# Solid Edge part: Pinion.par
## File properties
Author: Admin
Template: SEER_ExtSpurGear.par
Last saved by: Admin
Revision: 3
Application: Solid Edge
Density: 7833.000 kg/m^3
Accuracy: 0.990
SEER_Parameters: SEERSG2#ER#4#ER#0.349065850398866#ER#0.003#ER#0.032#ER#0#ER#0.001#ER#0#ER#1#ER#1.2#ER#0.8#ER#10000#ER#1#ER#1#ER#30#ER#120#ER#0.0024#ER#0.0064#ER#0.01#ER#0.014#ER#0#ER#0#ER#6#ER#1000#ER#104.71975511966#ER#104.71975511966#ER#9.54#ER#9.54#ER#0.92#ER#1#ER#1#ER#1#ER#1#ER#0#ER#0#ER#1#ER#0#ER#0#ER#1#ER#0#ER#0#ER#0.08#ER#0.08#ER#0.008#ER#0.008#ER#0.025#ER#0.025#ER#0#ER#1140#ER#605#ER#0#ER#1140#ER#390#ER#12#ER#SweptProtrusion_1#ER#Pattern_1#ER#SweptProtrusion_1#ER#Pattern_1#ER##ER#E:\Project\3D\SoccerBot\Hardware\Gear.par#ER#0#ER#0#ER#ExtrudedProtrusion_4#ER#ExtrudedCutout_5#ER#ExtrudedProtrusion_4#ER#ExtrudedCutout_5#ER#0#ER#1#ER#0#ER#0#ER#False#ER#0
Username: Admin
Material: Steel
Face Style: Steel
Fill Style: ANSI32(Steel)
Virtual Style: Machined steel
Coef. of Thermal Exp: 1.3e-05
Thermal Conductivity: 32.0
Specific Heat: 481.0
Modulus of Elasticity: 199947953000.0
Poission's Ratio: 0.29
Yield Stress: 262000766.0
Ultimate Stress: 358527364.0
Elongation: 0.0
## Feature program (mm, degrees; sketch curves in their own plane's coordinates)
sketch for "unnamed Protrusion 1" plane through (0, 0, 0) normal (0, 0, 1) x-axis (1, 0, 0)
  circle centre (0, 0) radius 24.9235
extrude "unnamed Protrusion 1" add finite 14 along +normal
sketch for "unnamed Cutout 1" plane through (0, 0, 14) normal (0, 0, 1) x-axis (0, 1, 0)
extrude "unnamed Cutout 1" cut through along -normal
swept protrusion "SweptProtrusion_1"
swept protrusion "unnamed SweptProtrusion 1"
swept protrusion "unnamed SweptProtrusion 2"
swept protrusion "unnamed SweptProtrusion 3"
swept protrusion "unnamed SweptProtrusion 4"
swept protrusion "unnamed SweptProtrusion 5"
swept protrusion "unnamed SweptProtrusion 6"
swept protrusion "unnamed SweptProtrusion 7"
swept protrusion "unnamed SweptProtrusion 8"
swept protrusion "unnamed SweptProtrusion 9"
swept protrusion "unnamed SweptProtrusion 10"
swept protrusion "unnamed SweptProtrusion 11"
swept protrusion "unnamed SweptProtrusion 12"
swept protrusion "unnamed SweptProtrusion 13"
swept protrusion "unnamed SweptProtrusion 14"
swept protrusion "unnamed SweptProtrusion 15"
swept protrusion "unnamed SweptProtrusion 16"
swept protrusion "unnamed SweptProtrusion 17"
swept protrusion "unnamed SweptProtrusion 18"
swept protrusion "unnamed SweptProtrusion 19"
swept protrusion "unnamed SweptProtrusion 20"
swept protrusion "unnamed SweptProtrusion 21"
swept protrusion "unnamed SweptProtrusion 22"
swept protrusion "unnamed SweptProtrusion 23"
swept protrusion "unnamed SweptProtrusion 24"
swept protrusion "unnamed SweptProtrusion 25"
swept protrusion "unnamed SweptProtrusion 26"
swept protrusion "unnamed SweptProtrusion 27"
swept protrusion "unnamed SweptProtrusion 28"
swept protrusion "unnamed SweptProtrusion 29"
swept protrusion "unnamed SweptProtrusion 30"
swept protrusion "unnamed SweptProtrusion 31"
swept protrusion "unnamed SweptProtrusion 32"
swept protrusion "unnamed SweptProtrusion 33"
swept protrusion "unnamed SweptProtrusion 34"
swept protrusion "unnamed SweptProtrusion 35"
swept protrusion "unnamed SweptProtrusion 36"
swept protrusion "unnamed SweptProtrusion 37"
swept protrusion "unnamed SweptProtrusion 38"
swept protrusion "unnamed SweptProtrusion 39"
swept protrusion "unnamed SweptProtrusion 40"
swept protrusion "unnamed SweptProtrusion 41"
swept protrusion "unnamed SweptProtrusion 42"
swept protrusion "unnamed SweptProtrusion 43"
swept protrusion "unnamed SweptProtrusion 44"
swept protrusion "unnamed SweptProtrusion 45"
swept protrusion "unnamed SweptProtrusion 46"
swept protrusion "unnamed SweptProtrusion 47"
swept protrusion "unnamed SweptProtrusion 48"
swept protrusion "unnamed SweptProtrusion 49"
swept protrusion "unnamed SweptProtrusion 50"
swept protrusion "unnamed SweptProtrusion 51"
swept protrusion "unnamed SweptProtrusion 52"
swept protrusion "unnamed SweptProtrusion 53"
swept protrusion "unnamed SweptProtrusion 54"
swept protrusion "unnamed SweptProtrusion 55"
swept protrusion "unnamed SweptProtrusion 56"
swept protrusion "unnamed SweptProtrusion 57"
swept protrusion "unnamed SweptProtrusion 58"
swept protrusion "unnamed SweptProtrusion 59"
swept protrusion "unnamed SweptProtrusion 60"
swept protrusion "unnamed SweptProtrusion 61"
swept protrusion "unnamed SweptProtrusion 62"
swept protrusion "unnamed SweptProtrusion 63"
swept protrusion "unnamed SweptProtrusion 64"
swept protrusion "unnamed SweptProtrusion 65"
swept protrusion "unnamed SweptProtrusion 66"
swept protrusion "unnamed SweptProtrusion 67"
swept protrusion "unnamed SweptProtrusion 68"
swept protrusion "unnamed SweptProtrusion 69"
swept protrusion "unnamed SweptProtrusion 70"
swept protrusion "unnamed SweptProtrusion 71"
swept protrusion "unnamed SweptProtrusion 72"
swept protrusion "unnamed SweptProtrusion 73"
swept protrusion "unnamed SweptProtrusion 74"
swept protrusion "unnamed SweptProtrusion 75"
swept protrusion "unnamed SweptProtrusion 76"
swept protrusion "unnamed SweptProtrusion 77"
swept protrusion "unnamed SweptProtrusion 78"
swept protrusion "unnamed SweptProtrusion 79"
swept protrusion "unnamed SweptProtrusion 80"
swept protrusion "unnamed SweptProtrusion 81"
swept protrusion "unnamed SweptProtrusion 82"
swept protrusion "unnamed SweptProtrusion 83"
swept protrusion "unnamed SweptProtrusion 84"
swept protrusion "unnamed SweptProtrusion 85"
sketch for "ExtrudedProtrusion_9" plane through (0, 0, 14) normal (0, 0, 1) x-axis (-1, 0, 0)
  line (-2.8121, 8.6546) -> (-9.1, 6.6115)
  line (-9.1, 6.6115) -> (-9.1, -6.6115)
  line (-9.1, -6.6115) -> (-2.8121, -8.6546)
extrude "ExtrudedProtrusion_9" add finite 6.5 along +normal
sketch for "ExtrudedCutout_10" plane through (0, 0, 14) normal (0, 0, 1) x-axis (-1, 0, 0)
  circle centre (0, 0) radius 3.2
extrude "ExtrudedCutout_10" cut finite 77.8568 symmetric
sketch for "unnamed Cutout 2" plane through (0, 0, 14) normal (0, 0, 1) x-axis (-1, 0, 0)
  line (-8.1, 3.2) -> (-4.7, 3.2)
  line (-4.7, 3.2) -> (-4.7, -3.4147)
  line (-4.7, -3.4147) -> (-8.1, -3.2)
  line (-8.1, -3.2) -> (-8.1, 3.2)
extrude "unnamed Cutout 2" cut finite 45.8039 along +normal
sketch for "unnamed Cutout 3" plane through (9.1, 0, 17.25) normal (1, 0, 0) x-axis (0, 1, 0)
  circle centre (0, 0) radius 2
extrude "unnamed Cutout 3" cut to key point symmetric
base feature "unnamed BaseFeature 1"
sketch for "ExtrudedProtrusion_4" plane through (0, 0, 0) normal (0, 0, 1) x-axis (1, 0, 0)
  circle centre (0, 0) radius 25.7195
extrude "ExtrudedProtrusion_4" add finite 14 along +normal
sketch for "ExtrudedCutout_5" plane through (0, 0, 0) normal (0, 0, 1) x-axis (1, 0, 0)
  circle centre (0, 0) radius 25.7195
extrude "ExtrudedCutout_5" cut finite 14 along +normal
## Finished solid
Body 1: sheet body, 1 face, 2 edges, 0 vertices.
  Faces by surface: cylinder 1
  Edges by curve: circle 2
Body 2: solid body, 359 faces, 1062 edges, 704 vertices.
  Faces by surface: spline 258, cylinder 90, plane 11
  Edges by curve: spline 516, circle 351, intersection 173, line 22
Bounding box of the edges (mm; curved faces can reach further): 52.526 x 52.545 x 20.500, from (-26.2629, -26.2725, 0) to (26.2629, 26.2725, 20.5).
Cylindrical faces by radius (mm): R2 x2, R3.2 x1, R9.1 x1, R24.9235 x86, R25.7195 x1
Planar faces by outward normal: +x 2, +y 1, +z 3, -x 1, -z 1, oblique 3
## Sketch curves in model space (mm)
line (8.1, 0, 14) -> (9.1, 0, 14)
circle centre (0, 0, 14) radius 3.2
circle centre (0, 0, 14) radius 4.7
line (8.1, 3.2, 14) -> (4.7, 3.2, 14)
line (8.1, 0, 14) -> (8.1, 3.2, 14)
line (8.1, -3.2, 14) -> (4.7, -3.2, 14)
line (8.1, 0, 14) -> (8.1, -3.2, 14)
arc centre (0, 0, 14) radius 9.1 from (2.8121, -8.6546, 14) through (-9.0959, 0.2722, 14) to (2.8121, 8.6546, 14)
line (2.8121, -8.6546, 14) -> (9.1, -6.6115, 14)
line (9.1, -6.6115, 14) -> (9.1, 6.6115, 14)
line (9.1, 6.6115, 14) -> (2.8121, 8.6546, 14)
line (-1.7952, 5.5252, 14) -> (-5.8095, 0, 14)
line (-5.8095, 0, 14) -> (-1.7952, -5.5252, 14)
line (-1.7952, -5.5252, 14) -> (4.7, -3.4147, 14)
line (4.7, -3.4147, 14) -> (4.7, 3.4147, 14)
line (4.7, 3.4147, 14) -> (-1.7952, 5.5252, 14)
line (4.7, 0, 14) -> (8.1, 0, 14)
line (3.2, 0, 14) -> (4.7, 0, 14)
line (0, 0, 14) -> (3.2, 0, 14)
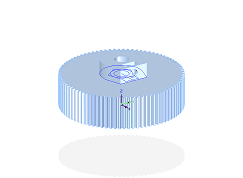
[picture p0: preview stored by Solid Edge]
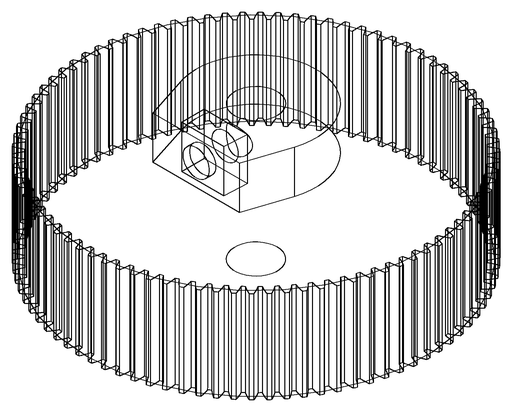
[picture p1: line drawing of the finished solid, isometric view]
